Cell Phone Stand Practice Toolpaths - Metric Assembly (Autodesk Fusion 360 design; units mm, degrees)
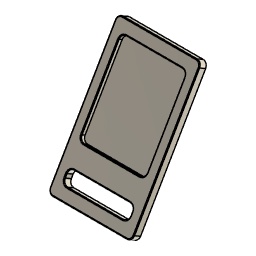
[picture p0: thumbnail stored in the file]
sketch "Main Body Sketch" plane through (0, 0, 0) normal (0, 1, 0) x axis (1, 0, 0)
  line L1 (30, 0) -> (-30, 0)
  line L2 (30, -100) -> (30, 0)
  line L3 (-30, -100) -> (30, -100)
  line L4 (-30, 0) -> (-30, -100)
  line L5 (30, -100) -> (-30, 0)
  line L6 (-30, -100) -> (30, 0)
  line L7 (23.5, -17.5) -> (-23.5, -17.5)
  line L8 (23.5, -8) -> (23.5, -17.5)
  line L9 (-23.5, -8) -> (23.5, -8)
  line L10 (-23.5, -17.5) -> (-23.5, -8)
  line L11 (0, 0) -> (0, -8)
  line L12 (23.5, -92) -> (-23.5, -92)
  line L13 (23.5, -32) -> (23.5, -92)
  line L14 (-23.5, -32) -> (23.5, -32)
  line L15 (-23.5, -92) -> (-23.5, -32)
  line L16 (0, -62.5) -> (0, -50)
  line L17 (17.2022, -62.0451) -> (0, -50)
  line L18 (21, -50) -> (0, -50)
  line L19 (17.2022, -37.9549) -> (0, -50)
  circle C1 centre (0, -50) radius 12.5
  point P6 (0, -50)
  point P1 (0, 0)
  point P11 (0, -8)
  point P12 (0, 0)
  point P17 (0, -50)
  point P21 (0, -50)
  point P22 (0, -62.5)
  point P18 (17.2022, -62.0451)
  point P23 (17.2022, -62.0451)
  point P19 (21, -50)
  point P24 (21, -50)
  point P25 (0, -50)
  point P20 (17.2022, -37.9549)
  point P26 (17.2022, -37.9549)
  point P27 (-17.2022, -62.0451)
  point P28 (-21, -50)
  point P29 (-17.2022, -37.9549)
  point P30 (0, -25)
  point P4 (30, -100)
  point P5 (-30, -100)
  point P3 (30, 0)
  point P8 (23.5, -17.5)
  point P9 (23.5, -8)
  point P7 (-23.5, -17.5)
  point P14 (23.5, -92)
  point P15 (23.5, -32)
  horizontal L1
  perpendicular L1 L2
  parallel L1 L3
  parallel L2 L4
  coincident L5 P6
  coincident L6 P6
  midpoint P1 L1
  horizontal L7
  vertical L8
  horizontal L9
  vertical L10
  midpoint L9 P11
  coincident P1 P12
  vertical L11
  horizontal L12
  vertical L13
  horizontal L14
  vertical L15
  collinear L8 L13
  collinear L10 L15
  coincident P6 P17
  coincident P6 P21
  coincident C1 P22
  vertical L16
  coincident P18 P23
  coincident P19 P24
  perpendicular L16 L18
  coincident P17 P25
  coincident P20 P26
  equal L17 L18
  equal L18 L19
  symmetric P18 L16 P27
  symmetric P19 L16 P28
  symmetric P20 L16 P29
  vertical P6 P30
  dimension "d1" distance P4 P5 = 60
  dimension "d2" distance P3 P4 = 100
  dimension "d3" distance P8 P9 = 9.5
  dimension "d4" distance L1 L9 = 8
  dimension "d5" distance P7 P8 = 47
  dimension "d6" distance L3 L12 = 8 (= "d4")
  dimension "d7" distance P14 P15 = 60
  dimension "d8" diameter C1 = 25
  dimension "d9" distance P21 P24 = 21
  dimension "d10" angle L17 L18 = 35
  dimension "d11" angle L18 L19 = 35 (= "d10")
  dimension "d12" distance P17 P30 = 25
  dimension "d15" R-Pattern1-uDistance = 21
  dimension "d16" R-Pattern1-vDistance = 0
extrude "Extrude1" new body sketch "Main Body Sketch" profile of L1 L2 L3 L4 L7 L8 L9 L10 L12 L13 L14 L15 C1 along normal blind 5.5
extrude "Extrude2" cut sketch "Main Body Sketch" profile of L12 L13 L14 L15 C1 along normal blind 3
fillet "Fillet1" radius 3.5
chamfer "Chamfer1" distance 0.5
move "Move1"
sketch "Stand Body Sketch" plane through (0, 0, 0) normal (1, 0, 0) x axis (0, 1, 0)
  line L1 (14.7999, 15.9408) -> (10.4698, 18.4408)
  line L2 (5.7198, 10.2135) -> (10.0499, 7.7135)
  line L3 (66.5456, 2.9579) -> (12.5794, 12.0948)
  line L4 (66.0448, 0) -> (66.5456, 2.9579)
  line L5 (-7.9029, 12.52) -> (66.0448, 0)
  line L6 (-6.317, 21.8867) -> (-7.9029, 12.52)
  line L7 (-2.3731, 21.2189) -> (-6.317, 21.8867)
  line L8 (-2.3281, 14.6188) -> (-2.3731, 21.2189)
  line L9 (6.5456, 13.1164) -> (-2.3281, 14.6188)
  line L10 (8.7802, 17.0486) -> (6.5456, 13.1164)
  line L11 (16.0467, 18.1003) -> (19.9906, 17.4326)
  line L12 (24.2831, 10.1133) -> (19.9906, 17.4326)
  line L13 (16.0467, 18.1003) -> (12.5794, 12.0948)
  line L14 (54.2999, 84.3568) -> (7.7999, 3.8164)
  line L15 (13.6992, 16.2157) -> (8.7802, 17.0486)
  line L16 (12.1028, 18.768) -> (11.7272, 16.5496)
  line L17 (16.0467, 18.1003) -> (12.1028, 18.768)
  line L18 (15.6711, 15.8819) -> (16.0467, 18.1003)
  line L19 (67.0881, 6.1623) -> (22.1368, 13.7729)
  line L20 (66.5456, 2.9579) -> (67.0881, 6.1623)
  circle C1 centre (13.6992, 16.2157) radius 2
  point P17 (24.2831, 10.1133)
  point P16 (16.0467, 18.1003)
  point P1 (0, 0)
  point P8 (66.0448, 0)
  point P18 (16.0467, 18.1003)
  point P5 (5.7198, 10.2135)
  point P23 (11.7272, 16.5496)
  point P26 (15.6711, 15.8819)
  point P21 (13.6992, 16.2157)
  point P22 (13.6992, 16.2157)
  point P25 (16.0467, 18.1003)
  point P28 (22.1368, 13.7729)
  point P30 (66.5456, 2.9579)
  point P7 (66.5456, 2.9579)
  point P9 (-7.9029, 12.52)
  point P10 (-6.317, 21.8867)
  point P11 (-2.3731, 21.2189)
  point P12 (-2.3281, 14.6188)
  point P13 (6.5456, 13.1164)
  point P15 (19.9906, 17.4326)
  point P14 (8.7802, 17.0486)
  point P27 (6.0499, 0.7853)
  perpendicular L3 L4
  perpendicular L5 L6
  perpendicular L6 L7
  parallel L3 L9
  coincident L3 P17
  collinear L7 L11
  perpendicular L1 L13
  coincident P16 L13
  parallel L3 L5
  horizontal P1 P8
  collinear L3 L9
  coincident P16 P18
  collinear L13 L14
  coincident P5 L5
  parallel L5 L15
  coincident C1 P23
  perpendicular L16 L17
  coincident C1 P26
  tangent C1 L18
  perpendicular L17 L18
  tangent C1 L16
  parallel L6 L16
  coincident P21 P22
  collinear L11 L17
  coincident P18 P25
  midpoint L12 P28
  perpendicular L4 L19
  coincident L3 P30
  perpendicular L3 L20
  coincident P7 P30
  dimension "d30" distance P8 P9 = 75
  dimension "d31" distance P7 P8 = 3
  dimension "d32" distance P9 P10 = 9.5
  dimension "d33" angle L11 L12 = 50
  dimension "d34" distance P10 P11 = 4
  dimension "d35" distance P12 P13 = 9
  dimension "d36" distance P15 P16 = 4
  dimension "d37" distance L9 P14 = 4.25
  dimension "d38" angle L9 L10 = 70
  dimension "d39" angle L8 L9 = 100
  dimension "d40" diameter C1 = 4
  dimension "d41" distance P8 P27 = 60
extrude "Extrude3" new body sketch "Stand Body Sketch" profile of L3 L4 L5 L6 L7 L8 L9 L10 L11 L12 L13 L14 L15 C1 L18 L19 L20 distance 40
fillet "Fillet2" radius 3.5
chamfer "Chamfer2" distance 0.5
sketch "Sketch3" plane through (0, -0.5658, 0.3267) normal (0, -0.866, 0.5) x axis (1, 0, 0)
  line L1 (-26.5, 103.2051) -> (26.5, 103.2051)
  line L2 (-29.5, 7.2051) -> (-29.5, 100.2051)
  line L3 (26.5, 4.2051) -> (-26.5, 4.2051)
  line L4 (29.5, 100.2051) -> (29.5, 7.2051)
  line L5 (-24, 92.2051) -> (-24, 39.2051)
  line L6 (20, 96.2051) -> (-20, 96.2051)
  line L7 (24, 39.2051) -> (24, 92.2051)
  line L8 (-20, 35.2051) -> (20, 35.2051)
  line L9 (20, 21.7051) -> (-20, 21.7051)
  line L10 (24, 15.2051) -> (24, 17.7051)
  line L11 (-20, 11.2051) -> (20, 11.2051)
  line L12 (-24, 17.7051) -> (-24, 15.2051)
  line L13 (29.5, 53.7051) -> (-29.5, 53.7051)
  line L14 (-37.5, -1.2949) -> (37.5, -1.2949)
  line L15 (-37.5, 108.7051) -> (-37.5, -1.2949)
  line L16 (37.5, 108.7051) -> (-37.5, 108.7051)
  line L17 (37.5, -1.2949) -> (37.5, 108.7051)
  line L18 (-37.5, 108.7051) -> (37.5, -1.2949)
  line L19 (37.5, 108.7051) -> (-37.5, -1.2949)
  arc A1 centre (-26.5, 100.2051) radius 3 clockwise from (-29.5, 100.2051) to (-26.5, 103.2051)
  arc A2 centre (-26.5, 7.2051) radius 3 clockwise from (-26.5, 4.2051) to (-29.5, 7.2051)
  arc A3 centre (26.5, 7.2051) radius 3 clockwise from (29.5, 7.2051) to (26.5, 4.2051)
  arc A4 centre (26.5, 100.2051) radius 3 clockwise from (26.5, 103.2051) to (29.5, 100.2051)
  arc A5 centre (-20, 92.2051) radius 4 clockwise from (-24, 92.2051) to (-20, 96.2051)
  arc A6 centre (20, 92.2051) radius 4 clockwise from (20, 96.2051) to (24, 92.2051)
  arc A7 centre (20, 39.2051) radius 4 clockwise from (24, 39.2051) to (20, 35.2051)
  arc A8 centre (-20, 39.2051) radius 4 clockwise from (-20, 35.2051) to (-24, 39.2051)
  arc A9 centre (20, 17.7051) radius 4 clockwise from (20, 21.7051) to (24, 17.7051)
  arc A10 centre (20, 15.2051) radius 4 clockwise from (24, 15.2051) to (20, 11.2051)
  arc A11 centre (-20, 15.2051) radius 4 clockwise from (-20, 11.2051) to (-24, 15.2051)
  arc A12 centre (-20, 17.7051) radius 4 clockwise from (-24, 17.7051) to (-20, 21.7051)
  point P38 (-29.5, 53.7051)
  point P39 (29.5, 53.7051)
  point P44 (0, 53.7051)
  point P42 (-37.5, 108.7051)
  point P43 (37.5, 108.7051)
  point P40 (37.5, -1.2949)
  midpoint L2 P38
  midpoint L4 P39
  horizontal L14
  perpendicular L14 L15
  parallel L14 L16
  parallel L15 L17
  coincident L18 P44
  coincident L19 P44
  midpoint L13 P44
  dimension "d47" distance P42 P43 = 75
  dimension "d48" distance P40 P43 = 110
extrude "Extrude4" sketch "Sketch3" profile of L1 A1 L2 A2 L3 A3 L4 A4 L5 A5 L6 A6 L7 A7 L8 A8 L9 A9 L10 A10 L11 A11 L12 A12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 blind 8 bodies "Main Body Stock"
named bodies: "Main Body", "Stand Body", "Main Body Stock"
